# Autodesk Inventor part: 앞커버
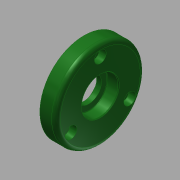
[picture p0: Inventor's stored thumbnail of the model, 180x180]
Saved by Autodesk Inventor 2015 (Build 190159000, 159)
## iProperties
Created: 2015-11
Part Number: 앞커버
Material: 알루미늄 6061
Document SubType Name: Modeling
Designer: mduedu
Density: 1 g/cm^3
Appearance: 매끄러움 - 짙은 산림 녹색
Author: mduedu
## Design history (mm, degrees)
sketch "스케치5"
  geometry: C1 r 30 at (0, 0); 2 further points
  constraints: 2 coincident, 1 centre point
  dimensions: "d66" = 60 diameter of C1
extrude "돌출2" new body sketch "스케치5" distance "d67" = 11; taper "d68" = 0 deg
sketch "스케치6"
  geometry: C1 r 16 at (0, 0); 1 further point
  constraints: 1 centre point, 1 coincident
  dimensions: "d69" = 32 diameter of C1
extrude "돌출3" join sketch "스케치6" distance "d70" = 3; taper "d71" = 0 deg
hole "구멍7" diameter "d98" = 25; stored, may be unused: countersink angle "d102" = 90 deg, drill point angle "d104" = 0 deg; dims "d96" = 10, "d97" = 10, "d99" = 6, "d100" = 4, "d101" = 2, "d103" = 3
hole "구멍8" diameter "d107" = 25; stored, may be unused: countersink angle "d111" = 90 deg, drill point angle "d113" = 0 deg; dims "d105" = 10, "d106" = 10, "d108" = 6, "d109" = 4, "d110" = 2, "d112" = 7.7
hole "구멍9" diameter "d116" = 17; stored, may be unused: countersink angle "d120" = 90 deg, drill point angle "d122" = 0 deg; dims "d114" = 10, "d115" = 10, "d117" = 6, "d118" = 4, "d119" = 2, "d121" = 7.7
chamfer "모따기2" distance "d123" = 0.6; stored, may be unused: second distance "d124" = 2, angle "d125" = 30 deg
fillet "모깎기11" dims "d126" = 0.3
fillet "모깎기13" dims "d128" = 3
fillet "모깎기14" dims "d129" = 3
fillet "모깎기15" dims "d130" = 0.3
sketch "스케치8" dims "d131" = 46
  geometry: 3 further points
  constraints: 2 vertical alignment, 1 coincident, 2 other
hole "구멍10" sketch "스케치8" at (0, 23) diameter "d132" = 4.5; stored, may be unused: countersink angle "d136" = 90 deg, drill point angle "d138" = 0 deg; dims "d133" = 6, "d134" = 8, "d135" = 4.6, "d137" = 7.7
node "솔리드2"
pattern_circular "원형 패턴4" dims angle "d140" = 360 deg
